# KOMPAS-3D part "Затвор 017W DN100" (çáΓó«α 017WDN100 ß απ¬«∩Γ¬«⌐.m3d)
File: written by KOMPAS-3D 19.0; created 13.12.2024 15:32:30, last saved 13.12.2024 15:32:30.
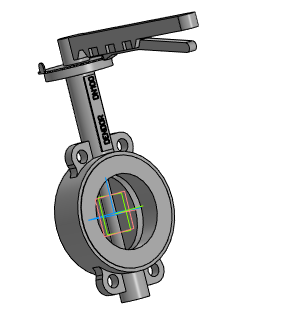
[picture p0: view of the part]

Document properties: Автор: Евгений; Полное имя файла: ..\Затвор 017WDN100.a3d

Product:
- Part/product: Затвор 017W DN100
    Масса: 16.1726

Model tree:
1. Операция без истории:1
